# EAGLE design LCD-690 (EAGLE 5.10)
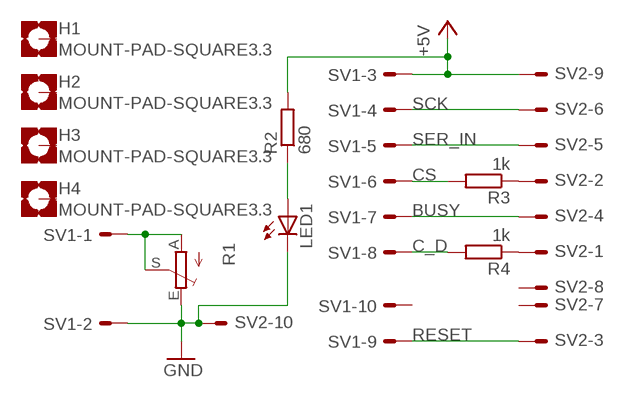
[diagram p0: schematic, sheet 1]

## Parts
H1  MOUNT-PAD-SQUARE3.3  [3,3-PAD-SQUARE]
H2  MOUNT-PAD-SQUARE3.3  [3,3-PAD-SQUARE]
H3  MOUNT-PAD-SQUARE3.3  [3,3-PAD-SQUARE]
H4  MOUNT-PAD-SQUARE3.3  [3,3-PAD-SQUARE]
LED1  LED3MM  [LED3MM]
R1  TRIM_EU-CA6H  [CA6H]
R2  680  R-EU_0207/10  [0207/10]
R3  1k  R-EU_0207/10  [0207/10]
R4  1k  R-EU_0207/10  [0207/10]
SV1  ML10E  [ML10]
SV2  ML10E  [ML10]

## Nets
+5V: R2.2 SV1.3 SV2.9
BUSY: SV1.7 SV2.4
C_D: R4.2 SV1.8
CS: R3.2 SV1.6
GND: LED1.K(C) R1.E SV1.2 SV2.10
N$1: R1.A R1.S SV1.1
N$2: LED1.A R2.1
N$3: R3.1 SV2.2
N$4: R4.1 SV2.1
RESET: SV1.9 SV2.3
SCK: SV1.4 SV2.6
SER_IN: SV1.5 SV2.5
Unconnected: H1.B3,3(MOUNT) H2.B3,3(MOUNT) H3.B3,3(MOUNT) H4.B3,3(MOUNT) SV1.10 SV2.7 SV2.8

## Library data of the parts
H1-H4 = holes:MOUNT-PAD-SQUARE: MOUNTING PAD, square
LED1 = bar-diode-trans:LED: LED
R1 = bar-rcl:TRIM_EU-: POTENTIOMETER
R2-R4 = bar-rcl:R-EU_: RESISTOR, European symbol
SV1 SV2 = bar-con:ML10E: HARTING

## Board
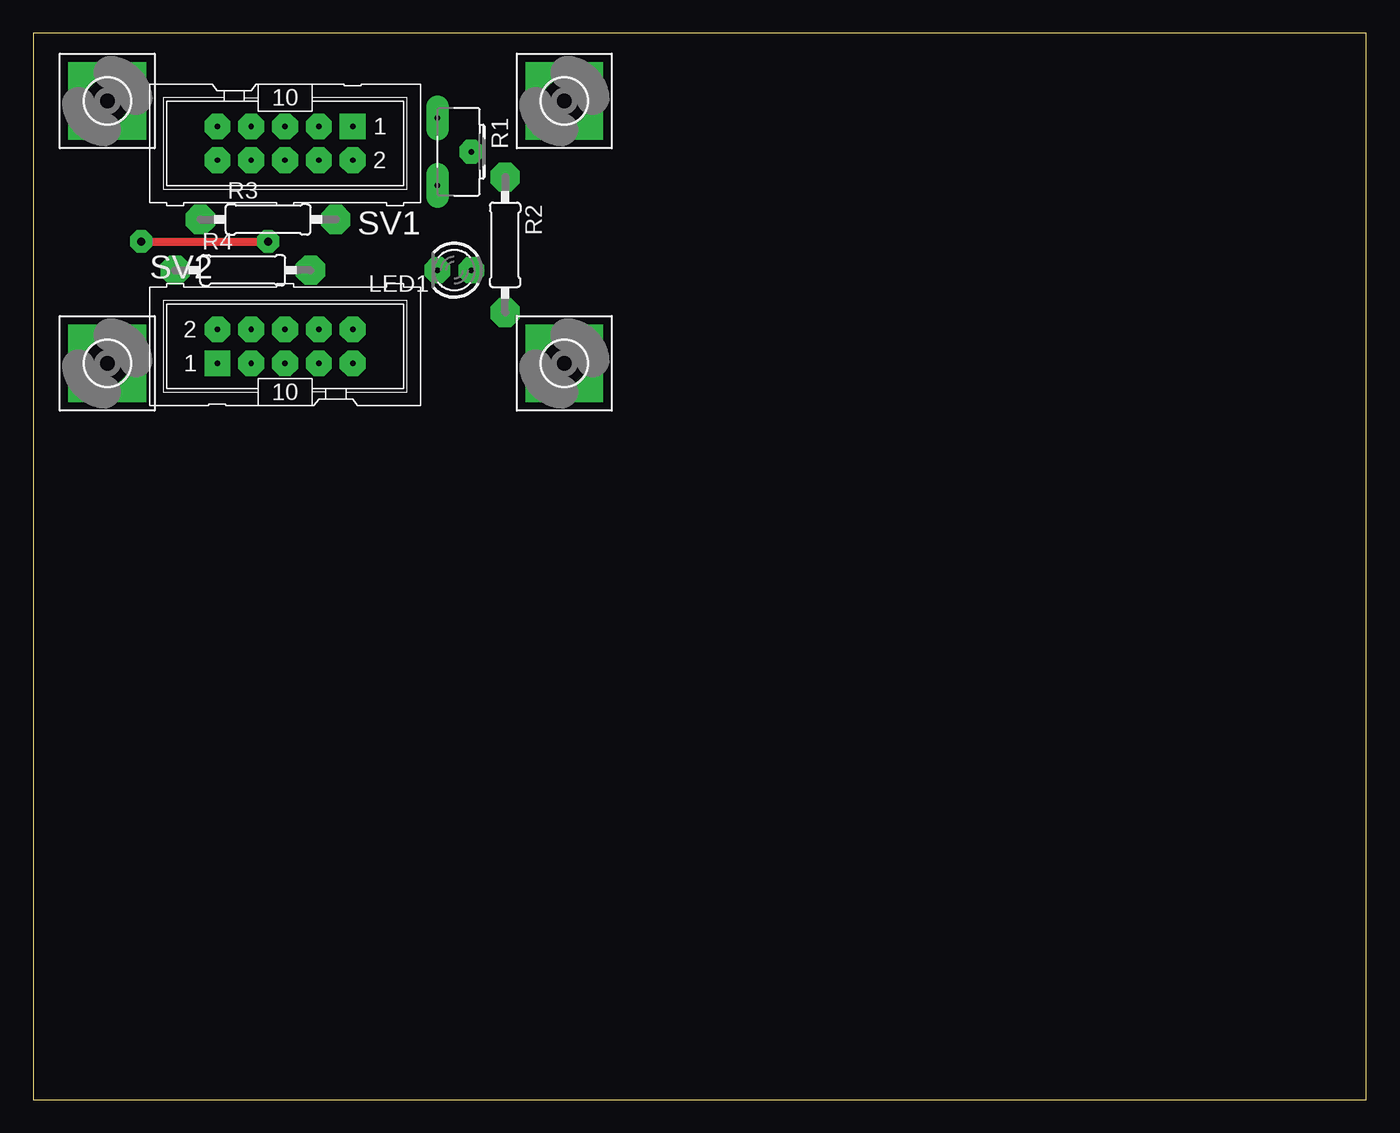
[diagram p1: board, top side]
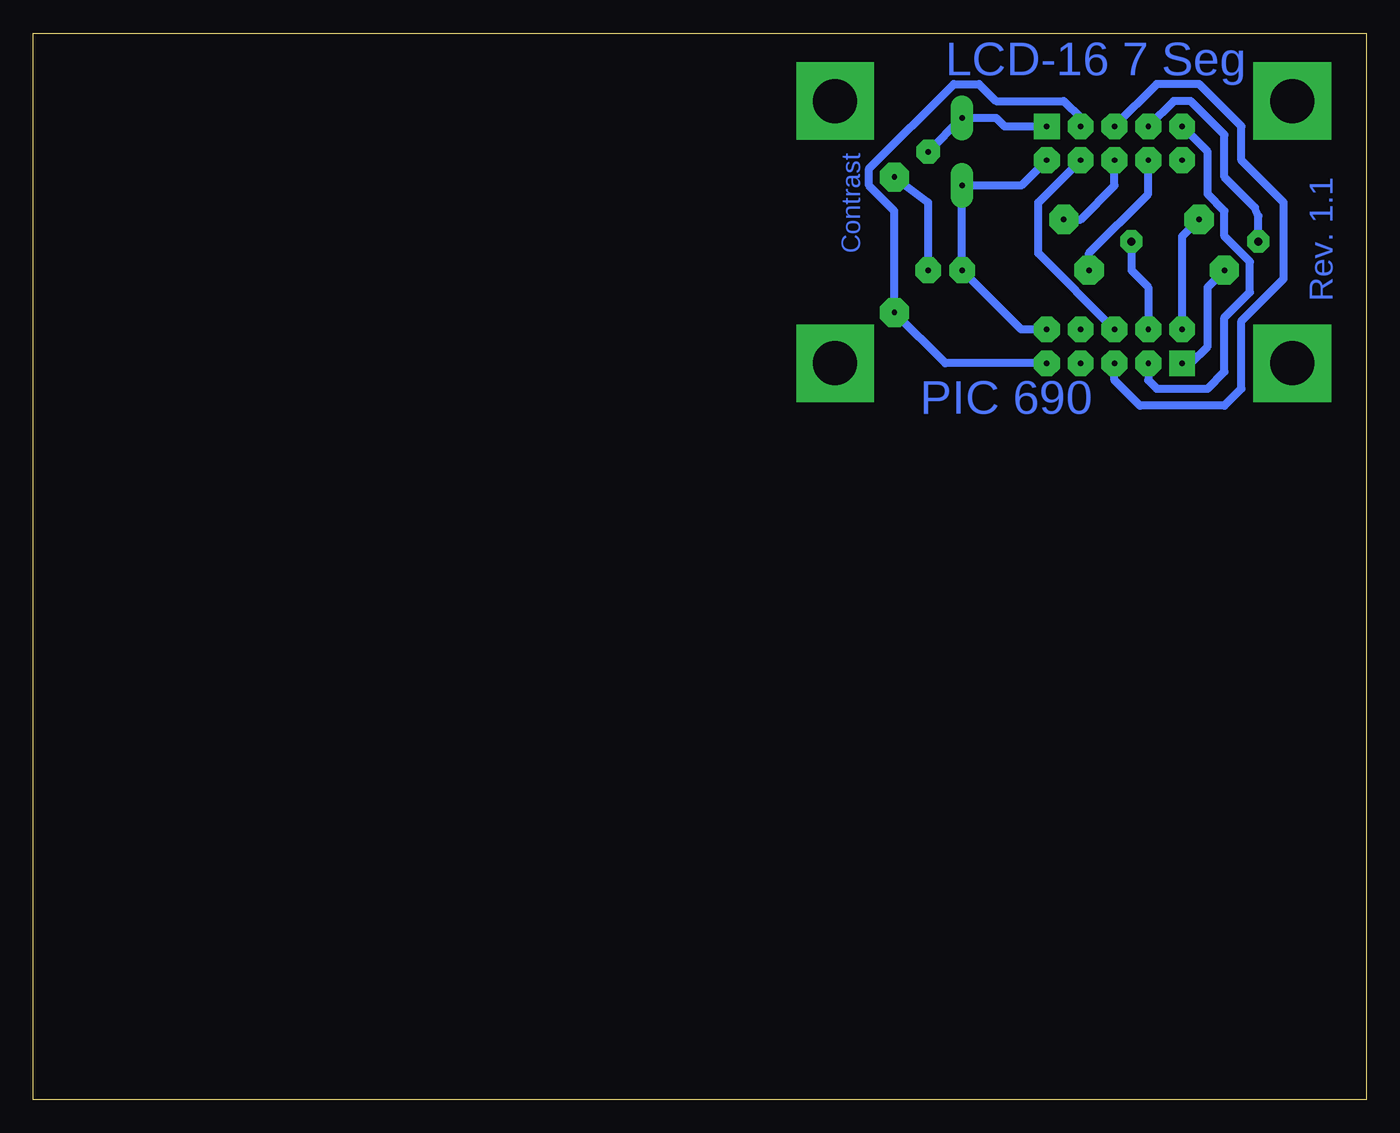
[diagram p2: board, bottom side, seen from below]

Size 100 x 80 mm. Coordinates in mm from the lower left corner, seen from the top.
Outline: 0,0 100,0 100,80 0,80 0,0
Copper layers (1*16): Top 0.035mm / dielectric 1.5mm / Bottom 0.035mm
Design rules "default": minimum track width 24mil, minimum drill 24mil, track to track 13mil, track to pad 13mil, pad to pad 13mil, via to via 13mil, smd to smd 13mil, copper to edge 40mil, drill to drill 8mil, minimum pad ring 10mil, minimum via ring 8mil, stop-mask expansion 4mil, vias tented up to drill 0mil, thermal gap 10mil

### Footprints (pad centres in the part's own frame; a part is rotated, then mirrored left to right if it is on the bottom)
3,3-PAD-SQUARE = drill 3.3 pad 5.842 square: B3,3 0,0
LED3MM = drill 0.406 pad 1.93 octagon: A -1.27,0; K 1.27,0
CA6H = drill 0.406 pad 1.676 long: A -2.54,0; E 2.54,0 | drill 0.406 pad 1.778 octagon: S 0,2.54
0207/10 = drill 0.406 pad 2.184 octagon: 1 -5.08,0; 2 5.08,0
ML10 = drill 0.406 pad 1.93 square: 1 -5.08,-1.27 | drill 0.406 pad 1.93 octagon: 2 -5.08,1.27; 3 -2.54,-1.27; 4 -2.54,1.27; 5 0,-1.27; 6 0,1.27; 7 2.54,-1.27; 8 2.54,1.27; 9 5.08,-1.27; 10 5.08,1.27

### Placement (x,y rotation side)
H1  5.55,55.24 0 top
H2  39.84,55.24 0 top
H3  5.55,74.92 0 top
H4  39.84,74.92 0 top
LED1  31.58,62.23 180 top
R1  30.31,71.11 270 top
R2  35.39,64.13 270 top
R3  17.61,66.03 0 top
R4  15.71,62.23 0 top
SV1  18.88,71.75 180 top
SV2  18.88,56.51 0 top

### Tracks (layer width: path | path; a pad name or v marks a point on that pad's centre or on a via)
+5V
  Bottom 0.61: SV2.9 31.58,55.24 R2.2 35.39,66.67 37.3,68.57 37.3,69.84 30.95,76.19 29.04,76.19 27.77,74.92 22.7,74.92 21.42,73.66 SV1.3
BUSY  (via drill 0.6 pad 1.68)
  Top 0.61: v8.09,64.38 v17.61,64.38
  Bottom 0.61: v17.61,64.38 17.61,62.23 16.34,60.96 SV2.4 | v8.09,64.38 8.09,66.29 8.34,66.92 10.63,69.21 10.63,72.38 13.17,74.92 14.44,74.92 SV1.7
C_D
  Bottom 0.61: R4.2 20.79,63.5 16.34,67.94 SV1.8
CS
  Bottom 0.61: R3.2 21.42,66.03 18.88,68.57 SV1.6
GND
  Bottom 0.61: SV2.10 25.87,57.78 LED1.K R1.E 25.87,68.57 SV1.2
N$1
  Bottom 0.61: R1.S R1.A 27.77,73.66 27.14,73.02 SV1.1
N$2
  Bottom 0.61: LED1.A 32.85,67.3 R2.1
N$3
  Bottom 0.61: SV2.2 13.81,64.77 R3.1
N$4
  Bottom 0.61: SV2.1 13.17,55.24 11.9,56.51 11.9,60.96 R4.1
RESET
  Bottom 0.61: SV2.3 16.34,53.97 15.71,53.34 11.9,53.34 10.63,54.61 10.63,58.67 8.73,60.57 8.73,62.86 10.63,64.77 10.63,66.67 11.9,67.94 11.9,69.84 11.9,71.11 SV1.9
SCK
  Bottom 0.61: SV2.6 24.6,63.5 24.6,67.3 SV1.4
SER_IN
  Bottom 0.61: SV2.5 18.88,53.97 16.98,52.07 10.63,52.07 9.36,53.34 9.36,58.41 6.18,61.59 6.18,67.3 9.36,70.48 9.36,73.02 12.54,76.19 15.71,76.19 SV1.5

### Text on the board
Bottom: LCD-16 7 Seg | Rev. 1.1 | Contrast | PIC 690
